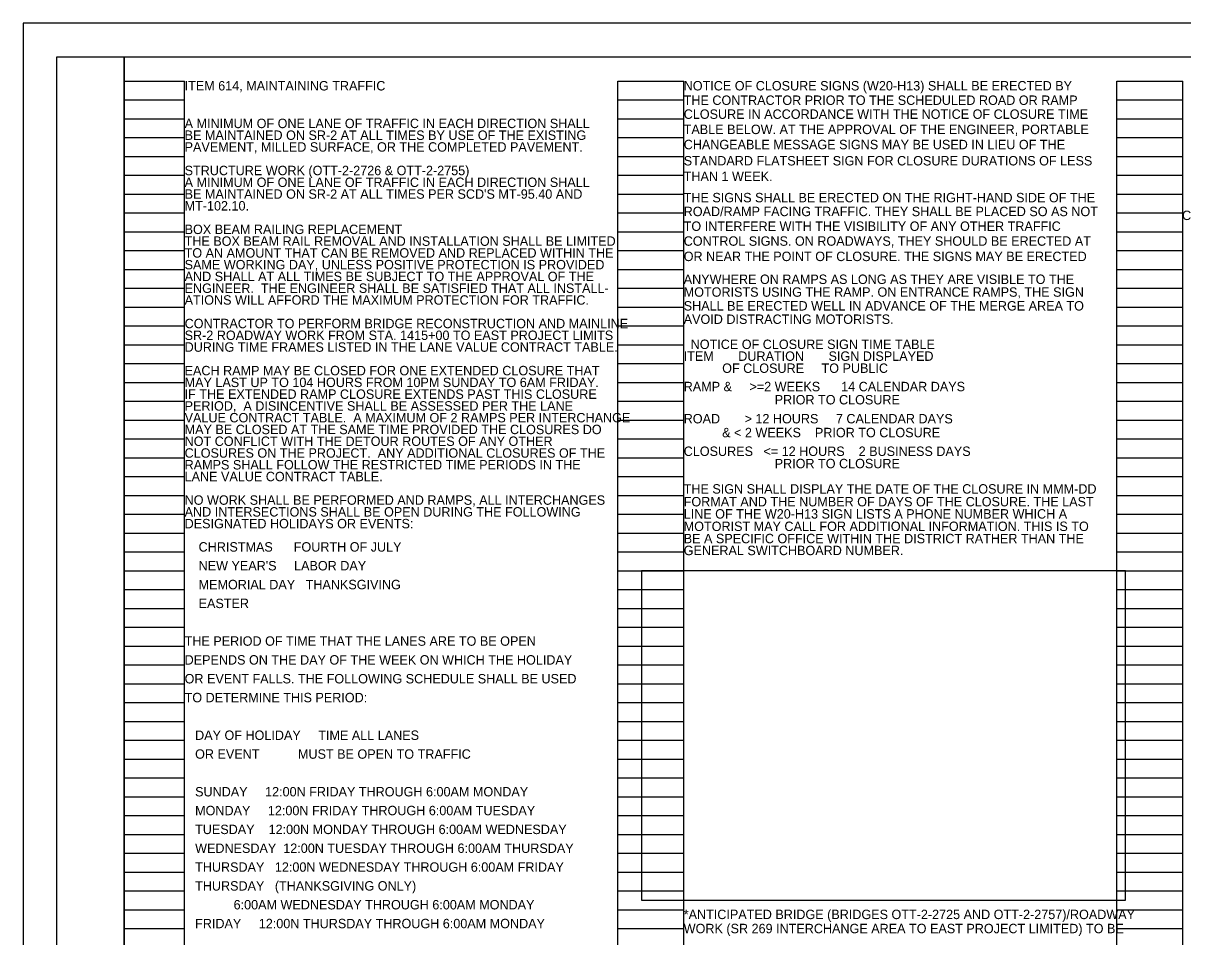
# Model space of a CAD drawing. Extents: x 0 to 34, y 0 to 22.
# Drawn here: x 0 to 17.24, y 8.42 to 22 of the extents above; entities that cross this region are included whole.
import ezdxf

# ---------------------------------------------------------------- set-up
doc = ezdxf.new("R2010")
doc.units = 0
for name, color, linetype in [('Default', 7, 'Continuous'), ('SH_Border', 7, 'Continuous'), ('SH_Cut_Line', 7, 'Continuous'), ('SH_Data', 7, 'Continuous'), ('SH_Text', 7, 'Continuous')]:
    doc.layers.add(name, color=color, linetype=linetype)

msp = doc.modelspace()

# ---------------------------------------------------------------- linework, layer by layer
at = {"layer": 'Default'}
msp.add_lwpolyline([(9.194, 8.963), (16.387, 8.963), (16.387, 13.859), (9.194, 13.859)], close=True, dxfattribs=at)
at = {"layer": 'SH_Border'}
for points in [[(0.5, 21.5), (1.5, 21.5), (1.5, 0.5), (0.5, 0.5)], [(1.5, 21.5), (33.5, 21.5), (33.5, 0.5), (1.5, 0.5)]]:
    msp.add_lwpolyline(points, close=True, dxfattribs=at)
at = {"layer": 'SH_Cut_Line'}
msp.add_lwpolyline([(0, 0), (34, 0), (34, 22), (0, 22)], close=True, dxfattribs=at)
at = {"layer": 'SH_Data'}
for p, q in [((1.5, 0.98), (1.5, 21.14)), ((1.5, 21.14), (2.4, 21.14)), ((2.4, 0.98), (2.4, 21.14)), ((8.84, 0.98), (8.84, 21.14)), ((8.84, 21.14), (9.82, 21.14)), ((9.82, 0.98), (9.82, 21.14)), ((16.26, 0.98), (16.26, 21.14)), ((16.26, 21.14), (17.24, 21.14)), ((17.24, 0.98), (17.24, 21.14)), ((1.5, 20.86), (2.4, 20.86)), ((8.84, 20.86), (9.82, 20.86)), ((16.26, 20.86), (17.24, 20.86)), ((1.5, 20.58), (2.4, 20.58)), ((8.84, 20.58), (9.82, 20.58)), ((16.26, 20.58), (17.24, 20.58)), ((1.5, 20.3), (2.4, 20.3)), ((8.84, 20.3), (9.82, 20.3)), ((16.26, 20.3), (17.24, 20.3)), ((1.5, 20.02), (2.4, 20.02)), ((8.84, 20.02), (9.82, 20.02)), ((16.26, 20.02), (17.24, 20.02)), ((1.5, 19.74), (2.4, 19.74)), ((8.84, 19.74), (9.82, 19.74)), ((16.26, 19.74), (17.24, 19.74)), ((1.5, 19.46), (2.4, 19.46)), ((8.84, 19.46), (9.82, 19.46)), ((16.26, 19.46), (17.24, 19.46)), ((1.5, 19.18), (2.4, 19.18)), ((8.84, 19.18), (9.82, 19.18)), ((16.26, 19.18), (17.24, 19.18)), ((1.5, 18.9), (2.4, 18.9)), ((8.84, 18.9), (9.82, 18.9)), ((16.26, 18.9), (17.24, 18.9)), ((1.5, 18.62), (2.4, 18.62)), ((8.84, 18.62), (9.82, 18.62)), ((16.26, 18.62), (17.24, 18.62)), ((1.5, 18.34), (2.4, 18.34)), ((8.84, 18.34), (9.82, 18.34)), ((16.26, 18.34), (17.24, 18.34)), ((1.5, 18.06), (2.4, 18.06)), ((8.84, 18.06), (9.82, 18.06)), ((16.26, 18.06), (17.24, 18.06)), ((1.5, 17.78), (2.4, 17.78)), ((8.84, 17.78), (9.82, 17.78)), ((16.26, 17.78), (17.24, 17.78)), ((1.5, 17.5), (2.4, 17.5)), ((8.84, 17.5), (9.82, 17.5)), ((16.26, 17.5), (17.24, 17.5)), ((1.5, 17.22), (2.4, 17.22)), ((8.84, 17.22), (9.82, 17.22)), ((16.26, 17.22), (17.24, 17.22)), ((1.5, 16.94), (2.4, 16.94)), ((8.84, 16.94), (9.82, 16.94)), ((16.26, 16.94), (17.24, 16.94)), ((1.5, 16.66), (2.4, 16.66)), ((8.84, 16.66), (9.82, 16.66)), ((16.26, 16.66), (17.24, 16.66)), ((1.5, 16.38), (2.4, 16.38)), ((8.84, 16.38), (9.82, 16.38)), ((16.26, 16.38), (17.24, 16.38)), ((1.5, 16.1), (2.4, 16.1)), ((8.84, 16.1), (9.82, 16.1)), ((16.26, 16.1), (17.24, 16.1)), ((1.5, 15.82), (2.4, 15.82)), ((8.84, 15.82), (9.82, 15.82)), ((16.26, 15.82), (17.24, 15.82)), ((1.5, 15.54), (2.4, 15.54)), ((8.84, 15.54), (9.82, 15.54)), ((16.26, 15.54), (17.24, 15.54)), ((1.5, 15.26), (2.4, 15.26)), ((8.84, 15.26), (9.82, 15.26)), ((16.26, 15.26), (17.24, 15.26)), ((1.5, 14.98), (2.4, 14.98)), ((8.84, 14.98), (9.82, 14.98)), ((16.26, 14.98), (17.24, 14.98)), ((1.5, 14.7), (2.4, 14.7)), ((8.84, 14.7), (9.82, 14.7)), ((16.26, 14.7), (17.24, 14.7)), ((1.5, 14.42), (2.4, 14.42)), ((8.84, 14.42), (9.82, 14.42)), ((16.26, 14.42), (17.24, 14.42)), ((1.5, 14.14), (2.4, 14.14)), ((8.84, 14.14), (9.82, 14.14)), ((16.26, 14.14), (17.24, 14.14)), ((1.5, 13.86), (2.4, 13.86)), ((8.84, 13.86), (9.82, 13.86)), ((16.26, 13.86), (17.24, 13.86)), ((1.5, 13.58), (2.4, 13.58)), ((8.84, 13.58), (9.82, 13.58)), ((16.26, 13.58), (17.24, 13.58)), ((1.5, 13.3), (2.4, 13.3)), ((8.84, 13.3), (9.82, 13.3)), ((16.26, 13.3), (17.24, 13.3)), ((1.5, 13.02), (2.4, 13.02)), ((8.84, 13.02), (9.82, 13.02)), ((16.26, 13.02), (17.24, 13.02)), ((1.5, 12.74), (2.4, 12.74)), ((8.84, 12.74), (9.82, 12.74)), ((16.26, 12.74), (17.24, 12.74)), ((1.5, 12.46), (2.4, 12.46)), ((8.84, 12.46), (9.82, 12.46)), ((16.26, 12.46), (17.24, 12.46)), ((1.5, 12.18), (2.4, 12.18)), ((8.84, 12.18), (9.82, 12.18)), ((16.26, 12.18), (17.24, 12.18)), ((1.5, 11.9), (2.4, 11.9)), ((8.84, 11.9), (9.82, 11.9)), ((16.26, 11.9), (17.24, 11.9)), ((1.5, 11.62), (2.4, 11.62)), ((8.84, 11.62), (9.82, 11.62)), ((16.26, 11.62), (17.24, 11.62)), ((1.5, 11.34), (2.4, 11.34)), ((8.84, 11.34), (9.82, 11.34)), ((16.26, 11.34), (17.24, 11.34)), ((1.5, 11.06), (2.4, 11.06)), ((8.84, 11.06), (9.82, 11.06)), ((16.26, 11.06), (17.24, 11.06)), ((1.5, 10.78), (2.4, 10.78)), ((8.84, 10.78), (9.82, 10.78)), ((16.26, 10.78), (17.24, 10.78)), ((1.5, 10.5), (2.4, 10.5)), ((8.84, 10.5), (9.82, 10.5)), ((16.26, 10.5), (17.24, 10.5)), ((1.5, 10.22), (2.4, 10.22)), ((8.84, 10.22), (9.82, 10.22)), ((16.26, 10.22), (17.24, 10.22)), ((1.5, 9.94), (2.4, 9.94)), ((8.84, 9.94), (9.82, 9.94)), ((16.26, 9.94), (17.24, 9.94)), ((1.5, 9.66), (2.4, 9.66)), ((8.84, 9.66), (9.82, 9.66)), ((16.26, 9.66), (17.24, 9.66)), ((1.5, 9.38), (2.4, 9.38)), ((8.84, 9.38), (9.82, 9.38)), ((16.26, 9.38), (17.24, 9.38)), ((1.5, 9.1), (2.4, 9.1)), ((8.84, 9.1), (9.82, 9.1)), ((16.26, 9.1), (17.24, 9.1)), ((1.5, 8.82), (2.4, 8.82)), ((8.84, 8.82), (9.82, 8.82)), ((16.26, 8.82), (17.24, 8.82)), ((1.5, 8.54), (2.4, 8.54)), ((8.84, 8.54), (9.82, 8.54)), ((16.26, 8.54), (17.24, 8.54))]:
    msp.add_line(p, q, dxfattribs=at)

# ---------------------------------------------------------------- texts
at = {"layer": 'Default'}
for s, p in [('A MINIMUM OF ONE LANE OF TRAFFIC IN EACH DIRECTION SHALL', (2.4, 20.44)), ('BE MAINTAINED ON SR-2 AT ALL TIMES BY USE OF THE EXISTING', (2.4, 20.265)), ('PAVEMENT, MILLED SURFACE, OR THE COMPLETED PAVEMENT.\xa0', (2.4, 20.09)), ('STRUCTURE WORK (OTT-2-2726 & OTT-2-2755)', (2.4, 19.74)), ('A MINIMUM OF ONE LANE OF TRAFFIC IN EACH DIRECTION SHALL', (2.4, 19.565)), ("BE MAINTAINED ON SR-2 AT ALL TIMES PER SCD'S MT-95.40 AND", (2.4, 19.39)), ('MT-102.10.', (2.4, 19.215)), ('COORDINATED/CONSTRUCTED AS TO ALLOW TRAFFIC CONTINUOUS', (17.229, 19.073)), ('BOX BEAM RAILING REPLACEMENT', (2.4, 18.865)), ('THE BOX BEAM RAIL REMOVAL AND INSTALLATION SHALL BE LIMITED', (2.4, 18.69)), ('TO AN AMOUNT THAT CAN BE REMOVED AND REPLACED WITHIN THE', (2.4, 18.515)), ('SAME WORKING DAY, UNLESS POSITIVE PROTECTION IS PROVIDED', (2.4, 18.34)), ('AND SHALL AT ALL TIMES BE SUBJECT TO THE APPROVAL OF THE', (2.4, 18.165)), ('ENGINEER.  THE ENGINEER SHALL BE SATISFIED THAT ALL INSTALL-', (2.4, 17.99)), ('ATIONS WILL AFFORD THE MAXIMUM PROTECTION FOR TRAFFIC.', (2.4, 17.815)), ('CONTRACTOR TO PERFORM BRIDGE RECONSTRUCTION AND MAINLINE', (2.4, 17.465)), ('SR-2 ROADWAY WORK FROM STA. 1415+00 TO EAST PROJECT LIMITS', (2.4, 17.29)), ('DURING TIME FRAMES LISTED IN THE LANE VALUE CONTRACT TABLE.', (2.4, 17.115)), ('EACH RAMP MAY BE CLOSED FOR ONE EXTENDED CLOSURE THAT', (2.4, 16.765)), ('MAY LAST UP TO 104 HOURS FROM 10PM SUNDAY TO 6AM FRIDAY.', (2.4, 16.59)), ('IF THE EXTENDED RAMP CLOSURE EXTENDS PAST THIS CLOSURE', (2.4, 16.415)), ('PERIOD,  A DISINCENTIVE SHALL BE ASSESSED PER THE LANE', (2.4, 16.24)), ('VALUE CONTRACT TABLE.  A MAXIMUM OF 2 RAMPS PER INTERCHANGE', (2.4, 16.065)), ('MAY BE CLOSED AT THE SAME TIME PROVIDED THE CLOSURES DO', (2.4, 15.89)), ('NOT CONFLICT WITH THE DETOUR ROUTES OF ANY OTHER', (2.4, 15.715)), ('CLOSURES ON THE PROJECT.  ANY ADDITIONAL CLOSURES OF THE', (2.4, 15.54)), ('RAMPS SHALL FOLLOW THE RESTRICTED TIME PERIODS IN THE', (2.4, 15.365)), ('LANE VALUE CONTRACT TABLE.', (2.4, 15.19))]:
    msp.add_text(s, height=0.14, dxfattribs=at).set_placement(p)
at = {"layer": 'SH_Text'}
for s, p in [('ITEM 614, MAINTAINING TRAFFIC', (2.4, 21)), ('NOTICE OF CLOSURE SIGNS (W20-H13) SHALL BE ERECTED BY', (9.82, 21)), ('THE CONTRACTOR PRIOR TO THE SCHEDULED ROAD OR RAMP', (9.82, 20.785)), ('CLOSURE IN ACCORDANCE WITH THE NOTICE OF CLOSURE TIME', (9.82, 20.578)), ('TABLE BELOW. AT THE APPROVAL OF THE ENGINEER, PORTABLE', (9.82, 20.351)), ('CHANGEABLE MESSAGE SIGNS MAY BE USED IN LIEU OF THE', (9.82, 20.126)), ('STANDARD FLATSHEET SIGN FOR CLOSURE DURATIONS OF LESS', (9.82, 19.885)), ('THAN 1 WEEK.', (9.82, 19.653)), ('THE SIGNS SHALL BE ERECTED ON THE RIGHT-HAND SIDE OF THE', (9.82, 19.337)), ('ROAD/RAMP FACING TRAFFIC. THEY SHALL BE PLACED SO AS NOT', (9.82, 19.131)), ('TO INTERFERE WITH THE VISIBILITY OF ANY OTHER TRAFFIC', (9.82, 18.912)), ('CONTROL SIGNS. ON ROADWAYS, THEY SHOULD BE ERECTED AT', (9.82, 18.691)), ('OR NEAR THE POINT OF CLOSURE. THE SIGNS MAY BE ERECTED', (9.82, 18.463)), ('ANYWHERE ON RAMPS AS LONG AS THEY ARE VISIBLE TO THE', (9.82, 18.123)), ('MOTORISTS USING THE RAMP. ON ENTRANCE RAMPS, THE SIGN', (9.82, 17.933)), ('SHALL BE ERECTED WELL IN ADVANCE OF THE MERGE AREA TO', (9.82, 17.728)), ('AVOID DISTRACTING MOTORISTS.', (9.82, 17.529)), ('  NOTICE OF CLOSURE SIGN TIME TABLE', (9.82, 17.156)), ('ITEM       DURATION       SIGN DISPLAYED', (9.82, 16.98)), ('           OF CLOSURE     TO PUBLIC', (9.82, 16.801)), ('RAMP &     >=2 WEEKS      14 CALENDAR DAYS', (9.82, 16.528)), ('                          PRIOR TO CLOSURE', (9.82, 16.332)), ('ROAD       > 12 HOURS     7 CALENDAR DAYS', (9.82, 16.05)), ('           & < 2 WEEKS    PRIOR TO CLOSURE', (9.82, 15.844)), ('CLOSURES   <= 12 HOURS    2 BUSINESS DAYS', (9.82, 15.566)), ('                          PRIOR TO CLOSURE', (9.82, 15.383)), ('THE SIGN SHALL DISPLAY THE DATE OF THE CLOSURE IN MMM-DD', (9.82, 15.006)), ('NO WORK SHALL BE PERFORMED AND RAMPS, ALL INTERCHANGES', (2.4, 14.84)), ('FORMAT AND THE NUMBER OF DAYS OF THE CLOSURE. THE LAST', (9.82, 14.816)), ('AND INTERSECTIONS SHALL BE OPEN DURING THE FOLLOWING', (2.4, 14.665)), ('LINE OF THE W20-H13 SIGN LISTS A PHONE NUMBER WHICH A', (9.82, 14.635)), ('DESIGNATED HOLIDAYS OR EVENTS:', (2.4, 14.49)), ('MOTORIST MAY CALL FOR ADDITIONAL INFORMATION. THIS IS TO', (9.82, 14.45)), ('BE A SPECIFIC OFFICE WITHIN THE DISTRICT RATHER THAN THE', (9.82, 14.268)), ('    CHRISTMAS      FOURTH OF JULY', (2.4, 14.144)), ('GENERAL SWITCHBOARD NUMBER.', (9.82, 14.091)), ("    NEW YEAR'S     LABOR DAY", (2.4, 13.864)), ('    MEMORIAL DAY   THANKSGIVING', (2.4, 13.584)), ('    EASTER', (2.4, 13.304)), ('THE PERIOD OF TIME THAT THE LANES ARE TO BE OPEN', (2.4, 12.744)), ('DEPENDS ON THE DAY OF THE WEEK ON WHICH THE HOLIDAY', (2.4, 12.464)), ('OR EVENT FALLS. THE FOLLOWING SCHEDULE SHALL BE USED', (2.4, 12.184)), ('TO DETERMINE THIS PERIOD:', (2.4, 11.904)), ('   DAY OF HOLIDAY     TIME ALL LANES', (2.4, 11.344)), ('   OR EVENT           MUST BE OPEN TO TRAFFIC', (2.4, 11.064)), ('   SUNDAY     12:00N FRIDAY THROUGH 6:00AM MONDAY', (2.4, 10.504)), ('   MONDAY     12:00N FRIDAY THROUGH 6:00AM TUESDAY', (2.4, 10.224)), ('   TUESDAY    12:00N MONDAY THROUGH 6:00AM WEDNESDAY', (2.4, 9.944)), ('   WEDNESDAY  12:00N TUESDAY THROUGH 6:00AM THURSDAY', (2.4, 9.664)), ('   THURSDAY   12:00N WEDNESDAY THROUGH 6:00AM FRIDAY', (2.4, 9.384)), ('   THURSDAY   (THANKSGIVING ONLY)', (2.4, 9.104)), ('              6:00AM WEDNESDAY THROUGH 6:00AM MONDAY', (2.4, 8.824)), ('*ANTICIPATED BRIDGE (BRIDGES OTT-2-2725 AND OTT-2-2757)/ROADWAY', (9.82, 8.68)), ('   FRIDAY     12:00N THURSDAY THROUGH 6:00AM MONDAY', (2.4, 8.544)), ('WORK (SR 269 INTERCHANGE AREA TO EAST PROJECT LIMITED) TO BE', (9.82, 8.47))]:
    msp.add_text(s, height=0.14, dxfattribs=at).set_placement(p)

doc.saveas('drawing.dxf')
